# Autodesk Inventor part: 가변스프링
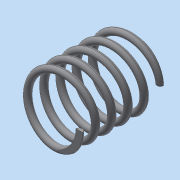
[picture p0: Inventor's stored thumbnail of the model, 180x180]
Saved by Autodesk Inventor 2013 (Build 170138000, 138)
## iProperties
Created: 2018-12
Part Number: 가변스프링
Material: 일반
Document SubType Name: Modeling
Designer: dgall
Density: 1 g/cm^3
Author: dgall
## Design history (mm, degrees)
sketch "스케치1"
  geometry: L1 (0, 0)-(9, 0); L2 (0, 0)-(0, 24.5); L3 (0, 24.5)-(9, 24.5); C1 r 1 at (9, 0)
  constraints: 6 end point, 2 perpendicular, 1 centre point, 1 coincident, 1 horizontal, 1 vertical alignment
  dimensions: "d0" = 24.5 distance of L1.start L2.end (derived); "d1" = 18 diameter of L1.end L2; "d3" = 2 diameter of C1
feature "코일1" pitch "d4" = 10; turns "d6" = 5; dims "d5" = 24.5 (= d0), "d7" = 0, angle "d8" = 90 deg, angle "d9" = 90 deg, "d10" = 0, "d11" = 0
node "작업 평면2"
  node "작업 평면1"
feature "분할1"
feature "분할2"
node "솔리드1"
other parameters: "d12" = 0, "d13" = 0
